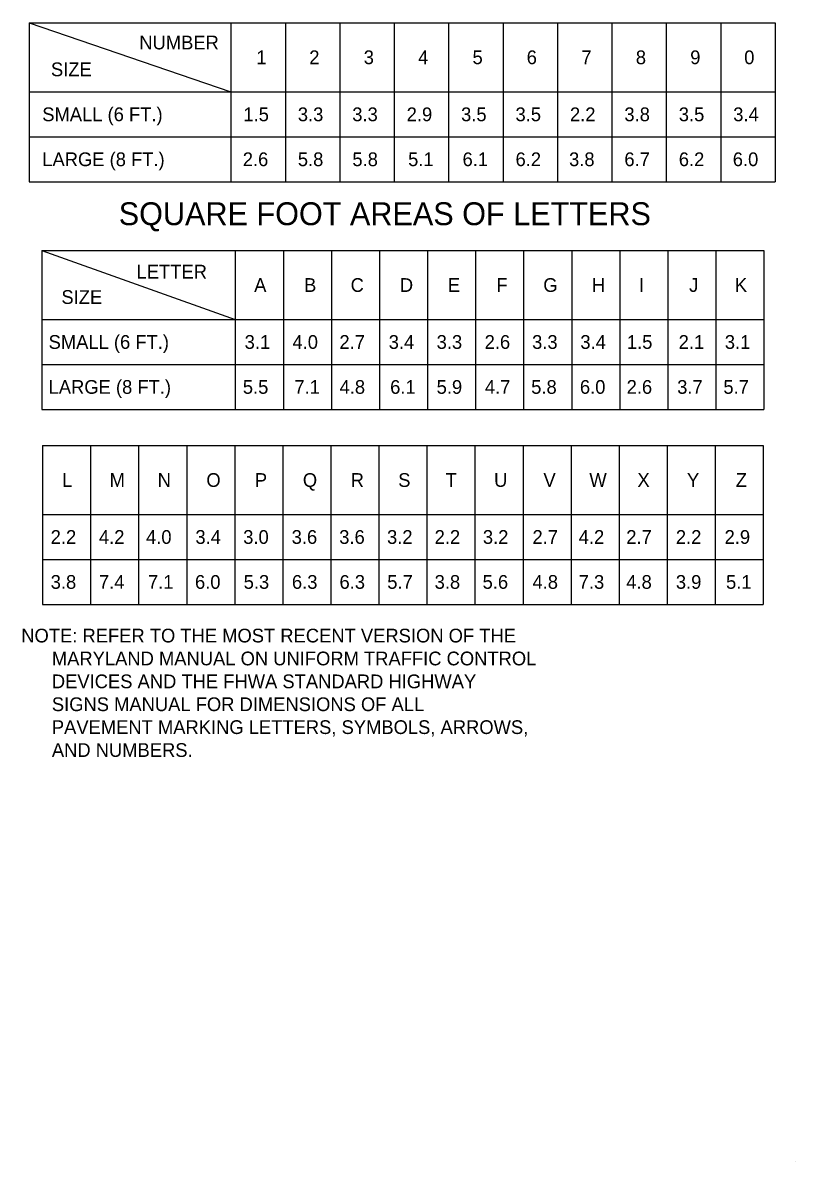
# Model space of a CAD drawing. Extents: x 9999.9 to 10007, y 10023.6 to 10033.8.
# Drawn here: x 10003.638 to 10007.014, y 10023.573 to 10028.546 of the extents above; entities that cross this region are included whole.
import ezdxf

# ---------------------------------------------------------------- set-up
doc = ezdxf.new("R2010")
doc.units = 0
doc.layers.add('DETL-NOTE', color=7, linetype='Continuous')
doc.layers.add('TTLB-TEXT', color=7, linetype='Continuous')

msp = doc.modelspace()

# ---------------------------------------------------------------- linework, layer by layer
at = {"layer": 'DETL-NOTE'}
for p, q in [((10003.6652, 10028.5461), (10004.5476, 10028.2443)), ((10003.6652, 10028.5461), (10006.9256, 10028.5461)), ((10003.6652, 10028.5461), (10003.6652, 10027.8515)), ((10004.5476, 10028.5461), (10004.5476, 10027.8515)), ((10004.7854, 10028.5461), (10004.7854, 10027.8515)), ((10005.0232, 10028.5461), (10005.0232, 10027.8515)), ((10005.261, 10028.5461), (10005.261, 10027.8515)), ((10005.4988, 10028.5461), (10005.4988, 10027.8515)), ((10005.7366, 10028.5461), (10005.7366, 10027.8515)), ((10005.9744, 10028.5461), (10005.9744, 10027.8515)), ((10006.2122, 10028.5461), (10006.2122, 10027.8515)), ((10006.45, 10028.5461), (10006.45, 10027.8515)), ((10006.6878, 10028.5461), (10006.6878, 10027.8515)), ((10006.9256, 10028.5461), (10006.9256, 10027.8515)), ((10003.6652, 10028.2443), (10006.9256, 10028.2443)), ((10003.6652, 10028.0479), (10006.9256, 10028.0479)), ((10003.6652, 10027.8515), (10006.9256, 10027.8515)), ((10003.7204, 10027.5515), (10003.7204, 10026.8569)), ((10003.7204, 10027.5515), (10004.5665, 10027.2497)), ((10003.7204, 10027.5515), (10006.8765, 10027.5515)), ((10004.5665, 10027.5515), (10004.5665, 10026.8569)), ((10004.7765, 10027.5515), (10004.7765, 10026.8569)), ((10004.9865, 10027.5515), (10004.9865, 10026.8569)), ((10005.1965, 10027.5515), (10005.1965, 10026.8569)), ((10005.4065, 10027.5515), (10005.4065, 10026.8569)), ((10005.6165, 10027.5515), (10005.6165, 10026.8569)), ((10005.8265, 10027.5515), (10005.8265, 10026.8569)), ((10006.0365, 10027.5515), (10006.0365, 10026.8569)), ((10006.2465, 10027.5515), (10006.2465, 10026.8569)), ((10006.4565, 10027.5515), (10006.4565, 10026.8569)), ((10006.6665, 10027.5515), (10006.6665, 10026.8569)), ((10006.8765, 10027.5515), (10006.8765, 10026.8569)), ((10003.7204, 10027.4461), (10003.7204, 10027.2497)), ((10003.7204, 10027.2497), (10006.8765, 10027.2497)), ((10003.7204, 10027.0533), (10006.8765, 10027.0533)), ((10003.7204, 10026.8569), (10006.8765, 10026.8569)), ((10003.7239, 10026.6996), (10003.7239, 10026.005)), ((10003.7239, 10026.6996), (10006.8739, 10026.6996)), ((10003.9339, 10026.6996), (10003.9339, 10026.005)), ((10004.1439, 10026.6996), (10004.1439, 10026.005)), ((10004.3539, 10026.6996), (10004.3539, 10026.005)), ((10004.5639, 10026.6996), (10004.5639, 10026.005)), ((10004.7739, 10026.6996), (10004.7739, 10026.005)), ((10004.9839, 10026.6996), (10004.9839, 10026.005)), ((10005.1939, 10026.6996), (10005.1939, 10026.005)), ((10005.4039, 10026.6996), (10005.4039, 10026.005)), ((10005.6139, 10026.6996), (10005.6139, 10026.005)), ((10005.8239, 10026.6996), (10005.8239, 10026.005)), ((10006.0339, 10026.6996), (10006.0339, 10026.005)), ((10006.2439, 10026.6996), (10006.2439, 10026.005)), ((10006.4539, 10026.6996), (10006.4539, 10026.005)), ((10006.6639, 10026.6996), (10006.6639, 10026.005)), ((10006.8739, 10026.6996), (10006.8739, 10026.005)), ((10003.7239, 10026.3978), (10006.8739, 10026.3978)), ((10003.7239, 10026.2014), (10006.8739, 10026.2014)), ((10003.7239, 10026.005), (10006.8153, 10026.005)), ((10006.8153, 10026.005), (10006.8739, 10026.005))]:
    msp.add_line(p, q, dxfattribs=at)
at = {"layer": 'TTLB-TEXT'}
msp.add_line((10007.0135, 10023.5725), (10007.0135, 10023.5725), dxfattribs=at)
msp.add_line((10007.0135, 10023.5725), (10007.0135, 10023.5725), dxfattribs=at)

# ---------------------------------------------------------------- texts
at = {"layer": 'DETL-NOTE'}
for s, height, p in [('NUMBER', 0.06, (10004.1469, 10028.4298)), ('1', 0.06, (10004.6582, 10028.3652)), ('2', 0.06, (10004.8897, 10028.3652)), ('3', 0.06, (10005.1276, 10028.3652)), ('4', 0.06, (10005.3654, 10028.3652)), ('5', 0.06, (10005.6032, 10028.3652)), ('6', 0.06, (10005.8399, 10028.3652)), ('7', 0.06, (10006.0789, 10028.3652)), ('8', 0.06, (10006.3168, 10028.3652)), ('9', 0.06, (10006.5546, 10028.3652)), ('0', 0.06, (10006.7905, 10028.3652)), ('SIZE', 0.06, (10003.7607, 10028.3126)), ('SMALL (6 FT.)', 0.06, (10003.7228, 10028.1161)), ('1.5', 0.06, (10004.6018, 10028.1161)), ('3.3', 0.06, (10004.8397, 10028.1161)), ('3.3', 0.06, (10005.0776, 10028.1161)), ('2.9', 0.06, (10005.3154, 10028.1161)), ('3.5', 0.06, (10005.5532, 10028.1161)), ('3.5', 0.06, (10005.791, 10028.1161)), ('2.2', 0.06, (10006.0289, 10028.1161)), ('3.8', 0.06, (10006.2668, 10028.1161)), ('3.5', 0.06, (10006.5046, 10028.1161)), ('3.4', 0.06, (10006.7425, 10028.1161)), ('LARGE (8 FT.)', 0.06, (10003.7228, 10027.9197)), ('2.6', 0.06, (10004.5991, 10027.9197)), ('5.8', 0.06, (10004.8397, 10027.9197)), ('5.8', 0.06, (10005.0781, 10027.9197)), ('5.1', 0.06, (10005.3217, 10027.9197)), ('6.1', 0.06, (10005.5595, 10027.9197)), ('6.2', 0.06, (10005.7911, 10027.9197)), ('3.8', 0.06, (10006.025, 10027.9197)), ('6.7', 0.06, (10006.2668, 10027.9197)), ('6.2', 0.06, (10006.5046, 10027.9197)), ('6.0', 0.06, (10006.7405, 10027.9197)), ('SQUARE FOOT AREAS OF LETTERS', 0.1, (10004.057, 10027.6619)), ('LETTER', 0.06, (10004.1349, 10027.4289)), ('A', 0.06, (10004.6489, 10027.3704)), ('B', 0.06, (10004.867, 10027.3704)), ('C', 0.06, (10005.0704, 10027.3704)), ('D', 0.06, (10005.2856, 10027.3704)), ('E', 0.06, (10005.4953, 10027.3704)), ('F', 0.06, (10005.7072, 10027.3704)), ('G', 0.06, (10005.9123, 10027.3704)), ('H', 0.06, (10006.1244, 10027.3704)), ('I', 0.06, (10006.3309, 10027.3704)), ('J', 0.06, (10006.5497, 10027.3704)), ('K', 0.06, (10006.7495, 10027.3704)), ('SIZE', 0.06, (10003.8065, 10027.3179)), ('SMALL (6 FT.)', 0.06, (10003.7505, 10027.1215)), ('3.1', 0.06, (10004.6072, 10027.1215)), ('4.0', 0.06, (10004.8162, 10027.1215)), ('2.7', 0.06, (10005.0216, 10027.1215)), ('3.4', 0.06, (10005.2369, 10027.1215)), ('3.3', 0.06, (10005.4463, 10027.1215)), ('2.6', 0.06, (10005.656, 10027.1215)), ('3.3', 0.06, (10005.8635, 10027.1215)), ('3.4', 0.06, (10006.0744, 10027.1215)), ('1.5', 0.06, (10006.2777, 10027.1215)), ('2.1', 0.06, (10006.5039, 10027.1215)), ('3.1', 0.06, (10006.7058, 10027.1215)), ('LARGE (8 FT.)', 0.06, (10003.7505, 10026.9251)), ('5.5', 0.06, (10004.5993, 10026.9251)), ('7.1', 0.06, (10004.8245, 10026.9251)), ('4.8', 0.06, (10005.0221, 10026.9251)), ('6.1', 0.06, (10005.2432, 10026.9251)), ('5.9', 0.06, (10005.4463, 10026.9251)), ('4.7', 0.06, (10005.6572, 10026.9251)), ('5.8', 0.06, (10005.8596, 10026.9251)), ('6.0', 0.06, (10006.0724, 10026.9251)), ('2.6', 0.06, (10006.2766, 10026.9251)), ('3.7', 0.06, (10006.4976, 10026.9251)), ('5.7', 0.06, (10006.6995, 10026.9251)), ('L', 0.06, (10003.8096, 10026.5185)), ('M', 0.06, (10004.0171, 10026.5185)), ('N', 0.06, (10004.2271, 10026.5185)), ('O', 0.06, (10004.44, 10026.5185)), ('P', 0.06, (10004.6519, 10026.5185)), ('Q', 0.06, (10004.8617, 10026.5185)), ('R', 0.06, (10005.0706, 10026.5185)), ('S', 0.06, (10005.2785, 10026.5185)), ('T', 0.06, (10005.4854, 10026.5185)), ('U', 0.06, (10005.6973, 10026.5185)), ('V', 0.06, (10005.9131, 10026.5185)), ('W', 0.06, (10006.1138, 10026.5185)), ('X', 0.06, (10006.3239, 10026.5185)), ('Y', 0.06, (10006.5403, 10026.5185)), ('Z', 0.06, (10006.7536, 10026.5185)), ('2.2', 0.06, (10003.7596, 10026.2696)), ('4.2', 0.06, (10003.9704, 10026.2696)), ('4.0', 0.06, (10004.1763, 10026.2696)), ('3.4', 0.06, (10004.3922, 10026.2696)), ('3.0', 0.06, (10004.601, 10026.2696)), ('3.6', 0.06, (10004.8127, 10026.2696)), ('3.6', 0.06, (10005.0206, 10026.2696)), ('3.2', 0.06, (10005.2296, 10026.2696)), ('2.2', 0.06, (10005.4375, 10026.2696)), ('3.2', 0.06, (10005.6484, 10026.2696)), ('2.7', 0.06, (10005.8652, 10026.2696)), ('4.2', 0.06, (10006.0671, 10026.2696)), ('2.7', 0.06, (10006.275, 10026.2696)), ('2.2', 0.06, (10006.4918, 10026.2696)), ('2.9', 0.06, (10006.7047, 10026.2696)), ('3.8', 0.06, (10003.7596, 10026.0732)), ('7.4', 0.06, (10003.9704, 10026.0732)), ('7.1', 0.06, (10004.1846, 10026.0732)), ('6.0', 0.06, (10004.3902, 10026.0732)), ('5.3', 0.06, (10004.603, 10026.0732)), ('6.3', 0.06, (10004.8139, 10026.0732)), ('6.3', 0.06, (10005.0218, 10026.0732)), ('5.7', 0.06, (10005.2305, 10026.0732)), ('3.8', 0.06, (10005.4375, 10026.0732)), ('5.6', 0.06, (10005.6472, 10026.0732)), ('4.8', 0.06, (10005.8652, 10026.0732)), ('7.3', 0.06, (10006.0671, 10026.0732)), ('4.8', 0.06, (10006.275, 10026.0732)), ('3.9', 0.06, (10006.4918, 10026.0732)), ('5.1', 0.06, (10006.711, 10026.0732)), ('NOTE: REFER TO THE MOST RECENT VERSION OF THE ', 0.06, (10003.631, 10025.8389)), ('      MARYLAND MANUAL ON UNIFORM TRAFFIC CONTROL ', 0.06, (10003.631, 10025.7389)), ('      DEVICES AND THE FHWA STANDARD HIGHWAY ', 0.06, (10003.631, 10025.6389)), ('      SIGNS MANUAL FOR DIMENSIONS OF ALL ', 0.06, (10003.631, 10025.5389)), ('      PAVEMENT MARKING LETTERS, SYMBOLS, ARROWS, ', 0.06, (10003.631, 10025.4389)), ('      AND NUMBERS.', 0.06, (10003.631, 10025.3389))]:
    msp.add_text(s, height=height, dxfattribs=at).set_placement(p)

doc.saveas('drawing.dxf')
